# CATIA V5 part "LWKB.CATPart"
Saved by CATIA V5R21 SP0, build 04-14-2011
Part number: LWJB.SLDPRT
Bounding box of the stored display mesh (mm): x -1.362 to 1.338, y -0.976 to 1.024, z 2.1 to 2.7
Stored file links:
  C:\Users\user\Desktop\CATIA文件\0-最新文件(2025.3月之前的慎用)\LWKB\LWKB.CATPart
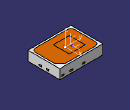
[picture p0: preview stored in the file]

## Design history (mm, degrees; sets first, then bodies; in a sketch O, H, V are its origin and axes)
AxisSystem1: origin (-0.0115, 0.0244, 2.7), X (0, 1, 0), Y (-1, 0, 0), Z (0, 0, 1)
Set1
  DatumSurface1 to DatumSurface42
  Line1: stored without definition
  Circle1: stored without definition
  Line2: stored without definition
  Circle2: stored without definition
  Line3: stored without definition
  Circle3: stored without definition
  Line4: stored without definition
  Circle4: stored without definition
  Line5: stored without definition
  Circle5: stored without definition
  Line6: stored without definition
  Circle6: stored without definition
  Line7: stored without definition
  Circle7: stored without definition
  Line8: stored without definition
  Line9: stored without definition
  Circle8: stored without definition
  Line10: stored without definition
  Line11: stored without definition
  Circle9: stored without definition
  Line12: stored without definition
  Line13: stored without definition
  Circle10: stored without definition
  Line14 to Line18: stored without definition
  Circle11: stored without definition
  Line19: stored without definition
  Circle12: stored without definition
  Line20: stored without definition
  Circle13: stored without definition
  Line21: stored without definition
  Circle14: stored without definition
  Line22: stored without definition
  Circle15: stored without definition
  Line23: stored without definition
  Circle16: stored without definition
  Line24: stored without definition
  Circle17: stored without definition
  Line25: stored without definition
  Circle18: stored without definition
  Line26: stored without definition
  Circle19: stored without definition
  Line27: stored without definition
  Circle20: stored without definition
  Line28 to Line30: stored without definition
  Circle21: stored without definition
  Line31: stored without definition
  Circle22: stored without definition
  Line32: stored without definition
  Circle23: stored without definition
  Line33: stored without definition
  Circle24: stored without definition
  Line34: stored without definition
  Line35: stored without definition
  Circle25: stored without definition
  Line36: stored without definition
  Circle26: stored without definition
  Line37: stored without definition
  Circle27: stored without definition
  Line38: stored without definition
  Circle28: stored without definition
  Line39: stored without definition
  Circle29: stored without definition
  Line40: stored without definition
  Circle30: stored without definition
  Line41: stored without definition
  Circle31: stored without definition
  Line42: stored without definition
  Circle32: stored without definition
  Line43: stored without definition
  Circle33: stored without definition
  Line44 to Line46: stored without definition
  Circle34: stored without definition
  Line47: stored without definition
  Circle35: stored without definition
  Line48: stored without definition
  Circle36: stored without definition
  Line49: stored without definition
  Circle37: stored without definition
  Line50: stored without definition
  Circle38: stored without definition
  Line51 to Line79: stored without definition
  DatumSurface43 to DatumSurface79
  Line80: stored without definition
  Circle39: stored without definition
  Line81: stored without definition
  Circle40: stored without definition
  Line82: stored without definition
  Circle41: stored without definition
  Line83: stored without definition
  Circle42: stored without definition
  Circle43: stored without definition
  Line84 to Line87: stored without definition
  Circle44: stored without definition
  Line88 to Line90: stored without definition
  Circle45: stored without definition
  Line91 to Line93: stored without definition
  Circle46: stored without definition
  Line94: stored without definition
  Line95: stored without definition
  Circle47: stored without definition
  Line96: stored without definition
  Circle48: stored without definition
  Line97: stored without definition
  Circle49: stored without definition
  Line98 to Line100: stored without definition
  Circle50: stored without definition
  Line101: stored without definition
  Circle51: stored without definition
  Line102: stored without definition
  Circle52: stored without definition
  Line103: stored without definition
  Circle53: stored without definition
  Line104: stored without definition
  Circle54: stored without definition
  Line105 to Line107: stored without definition
  Circle55: stored without definition
  Line108: stored without definition
  Circle56: stored without definition
  Line109 to Line112: stored without definition
  Circle57: stored without definition
  Line113: stored without definition
  Circle58: stored without definition
  Line114: stored without definition
  Circle59: stored without definition
  Line115 to Line117: stored without definition
  Circle60: stored without definition
  Line118: stored without definition
  Circle61: stored without definition
  Line119: stored without definition
  Circle62: stored without definition
  Line120: stored without definition
  Circle63: stored without definition
  Line121: stored without definition
  Circle64: stored without definition
  Line122 to Line124: stored without definition
  Circle65: stored without definition
  Line125: stored without definition
  Circle66: stored without definition
  Line126 to Line153: stored without definition
  DatumSurface80 to DatumSurface154
  DatumCurve1
  DatumCurve2
  Circle67: stored without definition
  Line154: stored without definition
  Circle68: stored without definition
  Line155: stored without definition
  Line156: stored without definition
  Circle69: stored without definition
  Line157: stored without definition
  Circle70: stored without definition
  Line158 to Line160: stored without definition
  Circle71: stored without definition
  Line161: stored without definition
  Circle72: stored without definition
  Line162 to Line164: stored without definition
  Circle73: stored without definition
  Line165: stored without definition
  Circle74: stored without definition
  Line166 to Line168: stored without definition
  Circle75: stored without definition
  Line169: stored without definition
  Circle76: stored without definition
  Line170: stored without definition
  Line171: stored without definition
  Circle77: stored without definition
  Line172: stored without definition
  Circle78: stored without definition
  Line173: stored without definition
  Circle79: stored without definition
  Line174 to Line176: stored without definition
  Circle80: stored without definition
  Line177: stored without definition
  Circle81: stored without definition
  Line178: stored without definition
  Circle82: stored without definition
  Line179: stored without definition
  Circle83: stored without definition
  Line180: stored without definition
  Circle84: stored without definition
  Line181 to Line183: stored without definition
  Circle85: stored without definition
  Line184: stored without definition
  Circle86: stored without definition
  Line185 to Line187: stored without definition
  Circle87: stored without definition
  Line188: stored without definition
  Line189: stored without definition
  Circle88: stored without definition
  Line190: stored without definition
  Line191: stored without definition
  Circle89: stored without definition
  Line192 to Line198: stored without definition
  Circle90: stored without definition
  Line199 to Line202: stored without definition
  Circle91: stored without definition
  Line203: stored without definition
  Line204: stored without definition
  Circle92: stored without definition
  Line205 to Line208: stored without definition
  Circle93: stored without definition
  Line209: stored without definition
  Line210: stored without definition
  Circle94: stored without definition
  Line211 to Line216: stored without definition
  Circle95: stored without definition
  Line217 to Line219: stored without definition
  Circle96: stored without definition
  Line220 to Line229: stored without definition
  Circle97: stored without definition
  Line230: stored without definition
  Circle98: stored without definition
  Line231: stored without definition
  Circle99: stored without definition
  Line232: stored without definition
  Circle100: stored without definition
  Line233: stored without definition
  Circle101: stored without definition
  Line234: stored without definition
  Circle102: stored without definition
  Line235: stored without definition
  Circle103: stored without definition
  Line236: stored without definition
  Circle104: stored without definition
  Line237 to Line245: stored without definition
  Circle105: stored without definition
  Line246: stored without definition
  Circle106: stored without definition
  Line247: stored without definition
  Circle107: stored without definition
  Line248: stored without definition
  Circle108: stored without definition
  Line249: stored without definition
  Circle109: stored without definition
  Line250: stored without definition
  Circle110: stored without definition
  Line251: stored without definition
  Circle111: stored without definition
  Line252: stored without definition
  Circle112: stored without definition
  Line253: stored without definition
  Circle113: stored without definition
  Line254: stored without definition
  Circle114: stored without definition
  Line255: stored without definition
  Circle115: stored without definition
  Line256: stored without definition
  Circle116: stored without definition
  Line257: stored without definition
  Circle117: stored without definition
  Line258 to Line260: stored without definition
  Circle118: stored without definition
  Line261: stored without definition
  Circle119: stored without definition
  Line262: stored without definition
  Circle120: stored without definition
  Line263: stored without definition
  Circle121: stored without definition
  Line264: stored without definition
  Circle122: stored without definition
  Line265: stored without definition
  Circle123: stored without definition
  Line266: stored without definition
  Circle124: stored without definition
  Line267: stored without definition
  Circle125: stored without definition
  Line268: stored without definition
  Circle126: stored without definition
  Line269: stored without definition
  Circle127: stored without definition
  Line270: stored without definition
  Circle128: stored without definition
  Line271 to Line273: stored without definition
  Circle129: stored without definition
  Line274: stored without definition
  Circle130: stored without definition
  Line275: stored without definition
  Circle131: stored without definition
  Line276: stored without definition
  Circle132: stored without definition
  Line277 to Line313: stored without definition
  DatumCurve3
  Line314: stored without definition
  DatumCurve4
  Line315: stored without definition
  DatumCurve5
  Line316: stored without definition
  DatumCurve6
  Line317: stored without definition
  DatumCurve7
  Line318 to Line323: stored without definition
  DatumCurve8
  DatumCurve9
  Line324: stored without definition
  DatumCurve10
  Line325: stored without definition
  DatumCurve11
  Line326: stored without definition
  DatumCurve12
  Line327 to Line335: stored without definition
  Point1 "几何中心（测试原点）": type Between, FirstPoint vertex [face of DatumSurface150], SecondPoint vertex [face of DatumSurface147], Ratio 0.5
  Point2 "虚拟坐标": (0.049, 0.345, -0.058), relative to Point1, in AxisSystem1
Body1 (main body)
